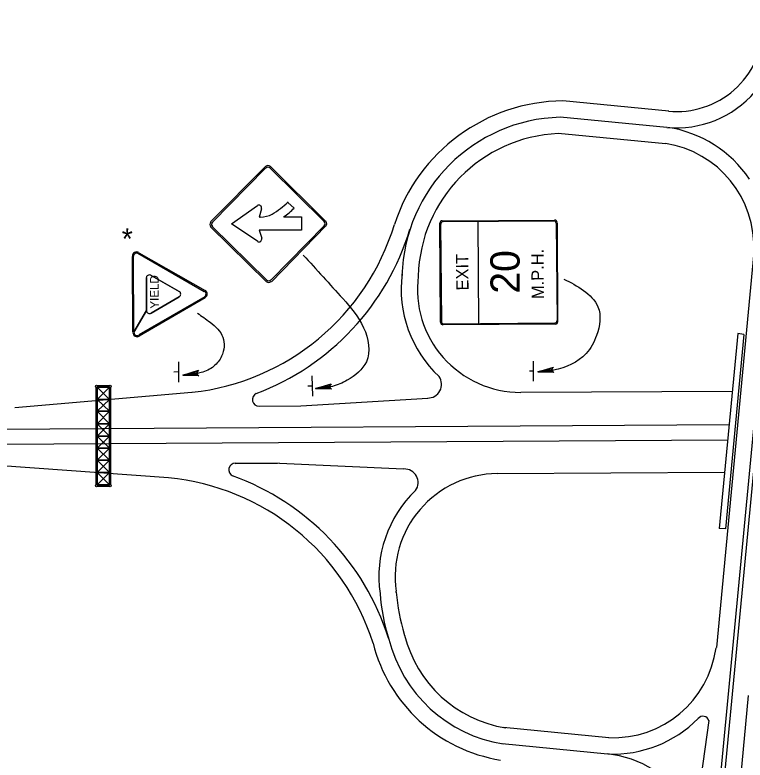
# Model space of a CAD drawing. Extents: x 640994 to 644422, y 298458 to 299646.
# Drawn here: x 641192.3 to 641393.3, y 298657.8 to 298862.8 of the extents above; entities that cross this region are included whole.
import ezdxf

# ---------------------------------------------------------------- set-up
doc = ezdxf.new("R2010")
doc.units = 0
doc.layers.add('2', color=7, linetype='Continuous')

msp = doc.modelspace()

# ---------------------------------------------------------------- linework, layer by layer
at = {"layer": '2'}
for p, q in [((641418.56, 298990.13), (641373.69, 298519.25)), ((641419.69, 298990.13), (641374.81, 298519.25)), ((641372.31, 298836.38), (641343.15, 298839.16)), ((641371.81, 298831.88), (641342.39, 298834.67)), ((641371.81, 298831.88), (641371.81, 298831.88)), ((641371.44, 298827.38), (641341.88, 298830.17)), ((641246.19, 298805.88), (641261.31, 298821.13)), ((641262.69, 298821.13), (641277.94, 298806)), ((641246.69, 298805.75), (641261.31, 298820.63)), ((641262.56, 298820.63), (641277.44, 298806)), ((641267.44, 298811.25), (641269.19, 298809.63)), ((641267.44, 298811.25), (641269.19, 298809.63)), ((641251.94, 298805.38), (641259.06, 298810.38)), ((641251.94, 298805.38), (641259.06, 298810.38)), ((641260.19, 298809.5), (641259.56, 298807.13)), ((641260.19, 298809.5), (641259.56, 298807.13)), ((641259.56, 298807.13), (641259.94, 298807.25)), ((641259.56, 298807.13), (641259.94, 298807.25)), ((641266.31, 298807.25), (641271.19, 298807.25)), ((641266.31, 298807.25), (641266.31, 298807.25)), ((641266.31, 298807.25), (641271.19, 298807.25)), ((641271.19, 298807.25), (641271.19, 298803.63)), ((641271.19, 298807.25), (641271.19, 298803.63)), ((641259.19, 298800.5), (641251.94, 298805.38)), ((641259.19, 298800.5), (641251.94, 298805.38)), ((641277.44, 298804.75), (641262.81, 298789.88)), ((641277.94, 298804.75), (641262.94, 298789.38)), ((641309.44, 298778.25), (641309.31, 298805.5)), ((641309.81, 298778.5), (641309.56, 298805.25)), ((641309.94, 298806.13), (641340.94, 298806.38)), ((641310.19, 298806), (641340.69, 298806.13)), ((641320.06, 298777.88), (641319.81, 298806)), ((641341.31, 298805.5), (641341.56, 298778.63)), ((641341.56, 298805.63), (641341.69, 298778.5)), ((641261.56, 298789.38), (641246.19, 298804.5)), ((641261.56, 298789.88), (641246.69, 298804.5)), ((641271.19, 298803.63), (641259.56, 298803.63)), ((641259.56, 298803.63), (641260.31, 298801.38)), ((641271.19, 298803.63), (641259.56, 298803.63)), ((641259.56, 298803.63), (641260.31, 298801.38)), ((641226.19, 298797.25), (641244.44, 298786.75)), ((641226.19, 298797.25), (641244.44, 298786.75)), ((641226.44, 298797.38), (641244.69, 298787)), ((641395.69, 298797.5), (641385.44, 298688.75)), ((641224.81, 298775.5), (641224.69, 298796.38)), ((641225.06, 298775.5), (641224.94, 298796.38)), ((641225.06, 298775.5), (641224.94, 298796.38)), ((641228.56, 298781.5), (641228.56, 298790.38)), ((641228.56, 298790.38), (641228.56, 298781.5)), ((641229.81, 298791.13), (641237.56, 298786.75)), ((641237.56, 298786.75), (641229.81, 298791.13)), ((641244.56, 298785.25), (641226.44, 298774.75)), ((641244.56, 298785.25), (641226.44, 298774.75)), ((641244.69, 298785), (641226.56, 298774.38)), ((641237.56, 298785.25), (641229.81, 298780.75)), ((641229.81, 298780.75), (641237.56, 298785.25)), ((641228.56, 298781.5), (641225.06, 298775.5)), ((641225.06, 298775.5), (641228.56, 298781.5)), ((641228.56, 298781.5), (641228.56, 298781.5)), ((641341.06, 298777.75), (641310.19, 298777.5)), ((641340.94, 298778), (641310.31, 298777.75)), ((641391.31, 298775.13), (641386.19, 298721.5)), ((641392.94, 298774.88), (641387.94, 298721.38)), ((641392.94, 298774.88), (641391.31, 298775.13)), ((641237.31, 298767.38), (641237.31, 298761.75)), ((641334.94, 298767.5), (641334.94, 298762)), ((641237.31, 298764.63), (641236.06, 298764.5)), ((641334.94, 298764.75), (641333.94, 298764.75)), ((641274.06, 298763.5), (641274.19, 298757.88)), ((641214.94, 298760.38), (641218.31, 298757)), ((641218.31, 298760.38), (641214.94, 298757)), ((641274.19, 298760.63), (641272.94, 298760.63)), ((641192.31, 298754.75), (641241.06, 298759)), ((641331.56, 298759), (641389.81, 298759.25)), ((641331.56, 298759), (641331.56, 298759)), ((641214.94, 298757), (641218.31, 298753.75)), ((641218.31, 298757), (641214.94, 298753.75)), ((641271.06, 298755.25), (641305.94, 298757.38)), ((641214.94, 298753.75), (641218.31, 298750.25)), ((641218.31, 298753.75), (641214.94, 298750.25)), ((641259.56, 298755.13), (641271.06, 298755.25)), ((641388.94, 298750), (641034.31, 298747.76)), ((641214.94, 298750.25), (641218.31, 298746.88)), ((641218.31, 298750.25), (641214.94, 298746.88)), ((641034.31, 298743.76), (641388.56, 298745.88)), ((641214.94, 298746.88), (641218.31, 298743.63)), ((641218.31, 298746.88), (641214.94, 298743.63)), ((641214.94, 298743.63), (641218.31, 298740.25)), ((641218.31, 298743.63), (641214.94, 298740.25)), ((641184.09, 298739.12), (641234.56, 298735.5)), ((641214.94, 298740.25), (641218.31, 298736.88)), ((641218.31, 298740.25), (641214.94, 298736.88)), ((641252.94, 298739.38), (641264.56, 298739.5)), ((641265.15, 298739.47), (641252.94, 298739.38)), ((641265.15, 298739.47), (641299.31, 298737.88)), ((641214.94, 298736.88), (641218.31, 298733.5)), ((641218.31, 298736.88), (641214.94, 298733.5)), ((641218.31, 298733.5), (641218.31, 298736.88)), ((641387.69, 298736.88), (641325.06, 298736.5)), ((641329.44, 298736.5), (641329.44, 298736.5)), ((641387.94, 298721.38), (641386.19, 298721.5)), ((641297.31, 298703.88), (641297.31, 298704.25)), ((641299.56, 298692.13), (641299.56, 298692.5)), ((641394.19, 298675.5), (641391.81, 298650.75)), ((641380.19, 298645.63), (641383.44, 298668.63)), ((641355.81, 298663.88), (641326.81, 298666.75)), ((641355.44, 298659.38), (641326.44, 298662.25))]:
    msp.add_line(p, q, dxfattribs=at)
for points in [[(641340.45, 298764.58), (641340.34, 298764.84), (641336.28, 298764.59), (641340.45, 298764.58), (641340.65, 298764.42), (641336.28, 298764.59), (641340.28, 298765.36), (641340.34, 298765.64), (641336.28, 298764.59), (641340.58, 298765.93), (641340.34, 298765.64)], [(641242.71, 298763.67), (641242.6, 298763.93), (641238.54, 298763.68), (641242.71, 298763.67), (641242.91, 298763.52), (641238.54, 298763.68), (641242.54, 298764.46), (641242.6, 298764.73), (641238.54, 298763.68), (641242.84, 298765.02), (641242.6, 298764.73)], [(641214.56, 298760.38), (641214.56, 298733.5)], [(641218.31, 298760.75), (641214.94, 298760.75)], [(641214.94, 298733.5), (641218.31, 298733.5), (641218.31, 298760.38), (641214.94, 298760.38), (641214.94, 298733.5)], [(641218.69, 298733.5), (641218.69, 298760.38)], [(641279.27, 298759.98), (641279.15, 298760.23), (641275.09, 298759.99), (641279.27, 298759.98), (641279.46, 298759.82), (641275.09, 298759.99), (641279.1, 298760.76), (641279.16, 298761.04), (641275.09, 298759.99), (641279.39, 298761.33), (641279.16, 298761.04)], [(641214.94, 298733.13), (641218.31, 298733.13)]]:
    msp.add_lwpolyline(points, dxfattribs=at)
for points in [[(641214.94, 298757), (641214.94, 298760.38), (641218.31, 298760.38), (641218.31, 298757)], [(641214.94, 298753.75), (641214.94, 298757), (641218.31, 298757), (641218.31, 298753.75)], [(641214.94, 298750.25), (641214.94, 298753.75), (641218.31, 298753.75), (641218.31, 298750.25)], [(641214.94, 298746.88), (641214.94, 298750.25), (641218.31, 298750.25), (641218.31, 298746.88)], [(641214.94, 298743.63), (641214.94, 298746.88), (641218.31, 298746.88), (641218.31, 298743.63)], [(641214.94, 298740.25), (641214.94, 298743.63), (641218.31, 298743.63), (641218.31, 298740.25)], [(641214.94, 298736.88), (641214.94, 298740.25), (641218.31, 298740.25), (641218.31, 298736.88)], [(641214.94, 298733.5), (641214.94, 298736.88), (641218.31, 298736.88), (641218.31, 298733.5)]]:
    msp.add_lwpolyline(points, close=True, dxfattribs=at)
for centre in [(641214.76, 298760.59), (641218.54, 298760.59), (641214.76, 298733.29), (641218.54, 298733.29)]:
    msp.add_circle(centre, 0.301, dxfattribs=at)
for centre, radius, start, end in [((641374.47, 298860.26), 24.02, 264.6308, 357.9333), ((641374.47, 298860.26), 28.5, 264.6308, 319.1479), ((641343.6, 298789.93), 49.23, 90.5215, 161.9821), ((641343.6, 298789.93), 44.75, 91.5424, 178.5076), ((641367.06, 298799.09), 33.15, 34.0358, 81.3457), ((641343.6, 298789.93), 40.27, 92.4413, 178.5076), ((641367.06, 298799.09), 28.67, 356.9079, 81.3457), ((641261.98, 298820.43), 0.932, 45.3747, 135.3747), ((641261.98, 298820.04), 0.854, 45.3747, 135.3747), ((641252.24, 298827), 21.86, 299.8117, 314.2596), ((641252.24, 298827), 21.86, 299.8117, 314.2596), ((641259.45, 298809.7), 0.776, 344.1725, 122.044), ((641259.45, 298809.7), 0.776, 344.1725, 122.044), ((641251.82, 298827.5), 24.91, 305.5161, 314.2639), ((641251.82, 298827.5), 24.91, 305.5161, 314.2639), ((641259.93, 298813.49), 6.31, 270.1504, 300.2643), ((641259.93, 298813.49), 6.31, 270.1504, 300.2643), ((641233.96, 298824.24), 65.66, 276.2555, 343.1031), ((641246.92, 298805.17), 0.932, 135.3747, 225.3747), ((641247.3, 298805.17), 0.854, 135.3747, 225.3747), ((641276.85, 298805.36), 0.854, 315.3747, 45.3747), ((641277.23, 298805.37), 0.932, 315.3747, 45.3747), ((641233.96, 298824.24), 70.14, 290.6825, 343.1031), ((641259.5, 298801.15), 0.777, 238.8177, 16.4645), ((641259.5, 298801.15), 0.777, 238.8177, 16.4645), ((641225.82, 298796.42), 1.18, 60.3746, 180.3747), ((641225.82, 298796.42), 0.871, 60.3746, 180.3747), ((641225.82, 298796.42), 0.871, 60.3746, 180.3747), ((641229.34, 298790.41), 0.871, 60.3747, 180.3747), ((641229.34, 298790.41), 0.871, 60.3747, 180.3747), ((641331.49, 298787.34), 32.86, 172.6333, 226.9648), ((641331.49, 298787.34), 28.38, 172.6333, 270.1695), ((641262.17, 298790.11), 0.932, 225.3747, 315.3747), ((641262.17, 298790.49), 0.854, 225.3747, 315.3747), ((641237.1, 298786), 0.871, 300.3747, 60.3746), ((641237.1, 298786), 0.871, 300.3747, 60.3746), ((641244.07, 298786.04), 0.871, 300.3747, 60.3746), ((641244.07, 298786.04), 0.871, 300.3747, 60.3746), ((641244.07, 298786.04), 1.18, 300.3747, 60.3746), ((641229.4, 298781.49), 0.871, 180.3746, 300.3746), ((641229.4, 298781.49), 0.871, 180.3746, 300.3746), ((641225.96, 298775.43), 1.18, 180.3747, 300.3747), ((641225.96, 298775.43), 0.871, 180.3746, 300.3747), ((641225.96, 298775.43), 0.871, 180.3746, 300.3747), ((641306, 298761.14), 3.76, 268.4553, 35.5224), ((641259.5, 298756.98), 1.81, 115.1781, 270.4845), ((641252.98, 298737.65), 1.81, 90.2638, 245.5703), ((641299.54, 298734.11), 3.76, 325.2259, 92.293), ((641228.32, 298670.07), 65.66, 17.6452, 84.4929), ((641228.32, 298670.07), 70.14, 17.6452, 70.0659), ((641325.36, 298708.24), 28.38, 90.5788, 188.115), ((641325.36, 298708.24), 32.86, 133.7836, 188.115), ((641349.03, 298707.89), 56.37, 184.3638, 197.375), ((641349.03, 298707.89), 51.89, 184.3638, 197.375), ((641332.87, 298700.48), 34.31, 194.0499, 260.8471), ((641332.87, 298700.48), 43.27, 194.0499, 260.8471), ((641332.87, 298700.48), 38.79, 194.0499, 260.8471), ((641356.93, 298692.56), 28.67, 267.7875, 352.2254), ((641381.74, 298668.16), 1.67, 14.023, 143.0689), ((641356.93, 298692.56), 33.15, 267.7875, 315.0975), ((641352.67, 298631.09), 28.5, 29.9854, 84.5024)]:
    msp.add_arc(centre, radius, start, end, dxfattribs=at)
for centre, major_axis, start_param, end_param in [((641309.96, 298805.49), (0.005, -0.717), 3.141593, 4.712389), ((641310.15, 298805.28), (0.004, -0.657), 3.141593, 4.712389), ((641340.75, 298805.48), (-0.004, 0.657), 4.712389, 6.283185), ((641340.94, 298805.69), (-0.005, 0.717), 4.712389, 6.283185), ((641310.14, 298778.25), (0.005, -0.717), 4.712389, 6.283185), ((641310.33, 298778.46), (0.004, -0.657), 4.712389, 6.283185), ((641340.92, 298778.66), (-0.004, 0.657), 3.141593, 4.712389), ((641341.11, 298778.45), (0.005, -0.717), 0, 1.570796)]:
    msp.add_ellipse(centre, major_axis=major_axis, ratio=0.9, start_param=start_param, end_param=end_param, dxfattribs=at)
for points in [[(641271.69, 298796.75), (641282.56, 298784.75), (641288.31, 298776.75), (641289.06, 298767.38), (641283.77, 298762.29), (641279.71, 298760.6), (641277.41, 298760.26)], [(641343.44, 298790.13), (641348.84, 298787.01), (641352.81, 298782.5), (641352.44, 298774.63), (641349.56, 298769.63), (641340.62, 298765.09), (641337.51, 298764.71)], [(641242.56, 298780.75), (641246.06, 298778.25), (641249.56, 298774.13), (641249.19, 298768.88), (641247.06, 298766.13), (641243.56, 298764.38), (641240.86, 298763.87)]]:
    msp.add_spline(points, degree=3, dxfattribs=at)

# ---------------------------------------------------------------- texts
msp.add_text('*', height=5.85, dxfattribs=at).set_placement((641221.72, 298798.29))
for s, height, rotation, p in [('EXIT', 3.387, 90.3745, (641317.19, 298787)), ('20', 8.061, 90.3746, (641331.31, 298786.13)), ('M.P.H.', 3.387, 90.3746, (641337.94, 298784.63)), ('YIELD', 2.383, 90.3738, (641231.94, 298782))]:
    msp.add_text(s, height=height, rotation=rotation, dxfattribs=at).set_placement(p)

doc.saveas('drawing.dxf')
